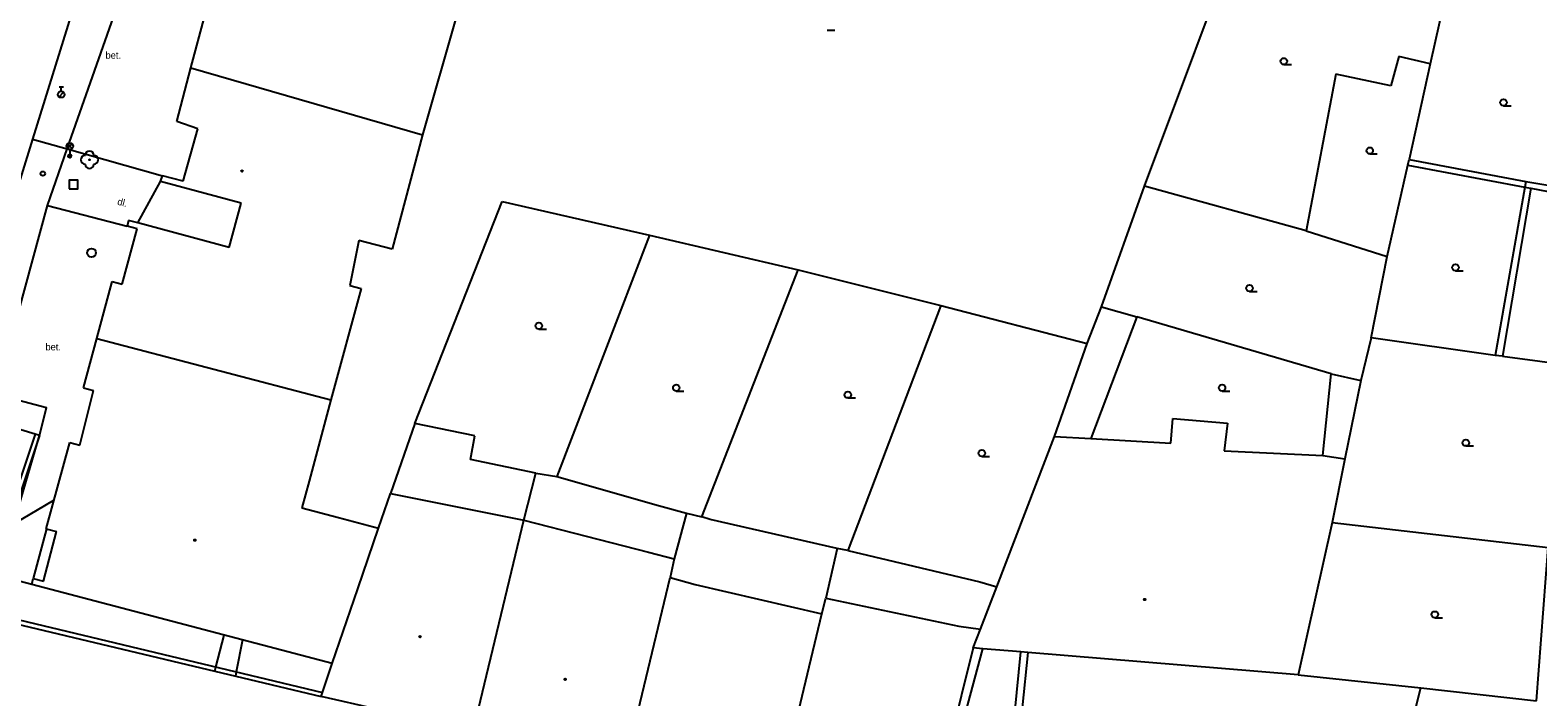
# Model space of a CAD drawing. Extents: x -599770 to -598493, y -1162076 to -1159209.
# Drawn here: x -599476.7 to -599389.9, y -1161736.9 to -1161698.5 of the extents above; entities that cross this region are included whole.
import ezdxf

# ---------------------------------------------------------------- set-up
doc = ezdxf.new("R2010")
doc.units = 0
doc.layers.add('Podklad', color=7, linetype='Continuous')

msp = doc.modelspace()

# ---------------------------------------------------------------- linework, layer by layer
at = {"layer": 'Podklad'}
for p, q in [((-599430.81, -1161698.538), (-599430.372, -1161698.538)), ((-599404.52, -1161700.517), (-599404.082, -1161700.517)), ((-599475.039, -1161702.366), (-599474.774, -1161702.101)), ((-599475.035, -1161701.793), (-599474.785, -1161701.793)), ((-599474.91, -1161702.043), (-599474.91, -1161701.793)), ((-599391.88, -1161702.887), (-599391.442, -1161702.887)), ((-599474.553, -1161705.35), (-599474.288, -1161705.085)), ((-599474.553, -1161705.085), (-599474.288, -1161705.35)), ((-599474.42, -1161705.405), (-599474.42, -1161705.78)), ((-599399.58, -1161705.657), (-599399.142, -1161705.657)), ((-599394.64, -1161712.378), (-599394.203, -1161712.378)), ((-599406.5, -1161713.567), (-599406.062, -1161713.567)), ((-599447.41, -1161715.738), (-599446.972, -1161715.738)), ((-599439.5, -1161719.297), (-599439.062, -1161719.297)), ((-599408.08, -1161719.297), (-599407.642, -1161719.297)), ((-599429.62, -1161719.698), (-599429.183, -1161719.698)), ((-599394.05, -1161722.457), (-599393.613, -1161722.457)), ((-599421.91, -1161723.058), (-599421.472, -1161723.058)), ((-599395.83, -1161732.347), (-599395.392, -1161732.347))]:
    msp.add_line(p, q, dxfattribs=at)
for points in [[(-599475.71, -1161708.62), (-599474.574, -1161705.36), (-599470.317, -1161693.246), (-599469.196, -1161690.055), (-599465.39, -1161677.84)], [(-599472.76, -1161692.57), (-599476.56, -1161704.8)], [(-599412.54, -1161707.52), (-599406.69, -1161691.89)], [(-599394.78, -1161694.54), (-599396.1, -1161700.47)], [(-599467.44, -1161700.7), (-599466.62, -1161697.63)], [(-599452.18, -1161697.79), (-599454.12, -1161704.55)], [(-599397.9, -1161700.05), (-599398.37, -1161701.74)], [(-599396.1, -1161700.47), (-599397.9, -1161700.05)], [(-599396.1, -1161700.47), (-599397.3, -1161705.97)], [(-599468.26, -1161703.79), (-599467.44, -1161700.7)], [(-599467.44, -1161700.7), (-599454.12, -1161704.55)], [(-599401.53, -1161701.06), (-599403.23, -1161710.09)], [(-599398.37, -1161701.74), (-599401.53, -1161701.06)], [(-599467.04, -1161704.22), (-599468.26, -1161703.79)], [(-599476.56, -1161704.8), (-599477.9, -1161709.16), (-599480.87, -1161720.49)], [(-599476.56, -1161704.8), (-599474.574, -1161705.36), (-599469.08, -1161706.91)], [(-599467.89, -1161707.23), (-599467.04, -1161704.22)], [(-599454.12, -1161704.55), (-599455.85, -1161711.14)], [(-599398.57, -1161711.55), (-599397.38, -1161706.31)], [(-599397.38, -1161706.31), (-599397.3, -1161705.97)], [(-599397.38, -1161706.31), (-599390.65, -1161707.57)], [(-599397.3, -1161705.97), (-599390.59, -1161707.25)], [(-599470.5, -1161709.62), (-599469.19, -1161707.24)], [(-599469.19, -1161707.24), (-599469.08, -1161706.91)], [(-599464.56, -1161708.49), (-599469.19, -1161707.24)], [(-599467.89, -1161707.23), (-599469.08, -1161706.91)], [(-599390.59, -1161707.25), (-599390.65, -1161707.57)], [(-599390.59, -1161707.25), (-599388.4, -1161707.6)], [(-599415.03, -1161714.45), (-599412.54, -1161707.52)], [(-599403.23, -1161710.09), (-599412.54, -1161707.52)], [(-599390.65, -1161707.57), (-599392.35, -1161717.25)], [(-599390.3, -1161707.63), (-599391.93, -1161717.29)], [(-599390.65, -1161707.57), (-599390.3, -1161707.63)], [(-599390.3, -1161707.63), (-599386.12, -1161708.43)], [(-599479.09, -1161720.98), (-599478.68, -1161719.49), (-599475.71, -1161708.62)], [(-599475.71, -1161708.62), (-599471.12, -1161709.82)], [(-599465.25, -1161711.04), (-599464.56, -1161708.49)], [(-599454.55, -1161721.16), (-599449.52, -1161708.39)], [(-599449.52, -1161708.39), (-599441.05, -1161710.34)], [(-599471.4, -1161713.15), (-599470.54, -1161709.97)], [(-599471.03, -1161709.48), (-599471.12, -1161709.82)], [(-599470.54, -1161709.97), (-599471.12, -1161709.82)], [(-599465.25, -1161711.04), (-599470.5, -1161709.62), (-599471.03, -1161709.48)], [(-599457.78, -1161710.63), (-599458.29, -1161713.23)], [(-599455.85, -1161711.14), (-599457.78, -1161710.63)], [(-599441.05, -1161710.34), (-599446.37, -1161724.22)], [(-599441.05, -1161710.34), (-599432.49, -1161712.33)], [(-599403.23, -1161710.09), (-599398.57, -1161711.55)], [(-599399.49, -1161716.24), (-599398.57, -1161711.55)], [(-599438.03, -1161726.53), (-599432.49, -1161712.33)], [(-599432.49, -1161712.33), (-599424.27, -1161714.38)], [(-599472.86, -1161716.28), (-599471.98, -1161713)], [(-599471.98, -1161713), (-599471.4, -1161713.15)], [(-599457.64, -1161713.4), (-599459.38, -1161719.8)], [(-599458.29, -1161713.23), (-599457.64, -1161713.4)], [(-599424.27, -1161714.38), (-599429.62, -1161728.47)], [(-599424.27, -1161714.38), (-599415.85, -1161716.56)], [(-599415.85, -1161716.56), (-599415.03, -1161714.45)], [(-599412.98, -1161715.03), (-599415.63, -1161722.03)], [(-599415.03, -1161714.45), (-599412.98, -1161715.03)], [(-599401.79, -1161718.3), (-599412.98, -1161715.03)], [(-599473.63, -1161719.11), (-599472.86, -1161716.28)], [(-599472.86, -1161716.28), (-599459.38, -1161719.8)], [(-599417.73, -1161721.92), (-599415.85, -1161716.56)], [(-599399.49, -1161716.24), (-599400.09, -1161718.7)], [(-599392.35, -1161717.25), (-599399.49, -1161716.24)], [(-599391.93, -1161717.29), (-599392.35, -1161717.25)], [(-599391.93, -1161717.29), (-599385.49, -1161718.16)], [(-599402.28, -1161723), (-599401.79, -1161718.3)], [(-599401.79, -1161718.3), (-599400.09, -1161718.7)], [(-599400.09, -1161718.7), (-599401.01, -1161723.19)], [(-599477.633, -1161726.927), (-599476.17, -1161721.85), (-599475.767, -1161720.261), (-599478.68, -1161719.49)], [(-599473.84, -1161722.41), (-599473.05, -1161719.26)], [(-599473.63, -1161719.11), (-599473.05, -1161719.26)], [(-599459.38, -1161719.8), (-599460.64, -1161724.48)], [(-599476.41, -1161721.77), (-599479.09, -1161720.98)], [(-599454.55, -1161721.16), (-599455.95, -1161725.2)], [(-599451.09, -1161721.88), (-599454.55, -1161721.16)], [(-599411.02, -1161722.3), (-599410.92, -1161720.87)], [(-599410.92, -1161720.87), (-599407.77, -1161721.14)], [(-599407.77, -1161721.14), (-599407.95, -1161722.74)], [(-599476.41, -1161721.77), (-599479.09, -1161729.79)], [(-599476.17, -1161721.85), (-599478.82, -1161729.77), (-599477.34, -1161732.47), (-599459.87, -1161736.65)], [(-599476.17, -1161721.85), (-599476.41, -1161721.77)], [(-599451.35, -1161723.24), (-599451.09, -1161721.88)], [(-599421.04, -1161730.56), (-599417.73, -1161721.92)], [(-599417.73, -1161721.92), (-599415.63, -1161722.03)], [(-599415.63, -1161722.03), (-599411.02, -1161722.3)], [(-599475.77, -1161727.22), (-599474.42, -1161722.26)], [(-599474.42, -1161722.26), (-599473.84, -1161722.41)], [(-599407.95, -1161722.74), (-599402.28, -1161723)], [(-599402.28, -1161723), (-599401.01, -1161723.19)], [(-599447.58, -1161724.02), (-599451.35, -1161723.24)], [(-599401.01, -1161723.19), (-599401.74, -1161726.86)], [(-599460.64, -1161724.48), (-599461.06, -1161726.02)], [(-599448.27, -1161726.72), (-599447.58, -1161724.02)], [(-599447.58, -1161724.02), (-599446.37, -1161724.22)], [(-599446.37, -1161724.22), (-599440.52, -1161725.88)], [(-599476.61, -1161730.42), (-599478.45, -1161729.94), (-599477.63, -1161726.93), (-599475.33, -1161725.57), (-599475.32, -1161725.56)], [(-599456.64, -1161727.18), (-599455.95, -1161725.2)], [(-599455.95, -1161725.2), (-599448.27, -1161726.72)], [(-599461.06, -1161726.02), (-599458.94, -1161726.58)], [(-599440.52, -1161725.88), (-599438.91, -1161726.32)], [(-599438.91, -1161726.32), (-599439.63, -1161728.95)], [(-599438.91, -1161726.32), (-599438.03, -1161726.53)], [(-599475.767, -1161727.221), (-599476.52, -1161730.08)], [(-599475.94, -1161730.23), (-599475.19, -1161727.37)], [(-599475.77, -1161727.22), (-599475.19, -1161727.37)], [(-599458.94, -1161726.58), (-599456.64, -1161727.18)], [(-599457.84, -1161730.67), (-599456.64, -1161727.18)], [(-599451.14, -1161738.62), (-599448.27, -1161726.72)], [(-599448.27, -1161726.72), (-599441.11, -1161728.57)], [(-599437.56, -1161726.69), (-599438.03, -1161726.53)], [(-599430.24, -1161728.35), (-599437.56, -1161726.69)], [(-599401.74, -1161726.86), (-599403.69, -1161735.62)], [(-599401.74, -1161726.86), (-599389.31, -1161728.29)], [(-599441.11, -1161728.57), (-599439.63, -1161728.95)], [(-599439.63, -1161728.95), (-599439.85, -1161730.03)], [(-599430.24, -1161728.35), (-599430.89, -1161731.22)], [(-599429.62, -1161728.47), (-599430.24, -1161728.35)], [(-599429.62, -1161728.47), (-599422.03, -1161730.27)], [(-599389.97, -1161737.13), (-599389.31, -1161728.29)], [(-599476.61, -1161730.42), (-599476.52, -1161730.08)], [(-599459.31, -1161734.98), (-599476.61, -1161730.42)], [(-599476.52, -1161730.08), (-599475.94, -1161730.23)], [(-599459.31, -1161734.98), (-599457.84, -1161730.67)], [(-599442.5, -1161741.05), (-599439.85, -1161730.03)], [(-599439.85, -1161730.03), (-599438.41, -1161730.42)], [(-599438.41, -1161730.42), (-599431.13, -1161732.11)], [(-599422.03, -1161730.27), (-599421.04, -1161730.56)], [(-599421.98, -1161733), (-599421.04, -1161730.56)], [(-599431.13, -1161732.11), (-599430.89, -1161731.22)], [(-599430.89, -1161731.22), (-599423.24, -1161732.82)], [(-599433.7, -1161742.87), (-599431.13, -1161732.11)], [(-599477.51, -1161732.69), (-599459.95, -1161736.88)], [(-599466.074, -1161735.419), (-599466.012, -1161735.18), (-599465.529, -1161733.341)], [(-599423.24, -1161732.82), (-599421.98, -1161733)], [(-599422.4, -1161734.08), (-599421.98, -1161733)], [(-599464.483, -1161733.617), (-599464.839, -1161735.461), (-599464.886, -1161735.702)], [(-599422.4, -1161734.08), (-599425.13, -1161745.05)], [(-599424.54, -1161744.83), (-599423.25, -1161739.32), (-599421.85, -1161734.12)], [(-599421.85, -1161734.12), (-599422.4, -1161734.08)], [(-599419.66, -1161734.3), (-599421.85, -1161734.12)], [(-599420.25, -1161740.15), (-599419.66, -1161734.3)], [(-599419.26, -1161734.34), (-599419.66, -1161734.3)], [(-599459.87, -1161736.65), (-599459.31, -1161734.98)], [(-599419.26, -1161734.34), (-599419.58, -1161737.52)], [(-599403.69, -1161735.62), (-599419.26, -1161734.34)], [(-599403.69, -1161735.62), (-599396.63, -1161736.37)], [(-599459.95, -1161736.88), (-599459.87, -1161736.65)], [(-599456.75, -1161737.6), (-599459.95, -1161736.88)], [(-599397.48, -1161739.72), (-599396.63, -1161736.37)], [(-599396.63, -1161736.37), (-599389.97, -1161737.13)]]:
    msp.add_lwpolyline(points, dxfattribs=at)
msp.add_lwpolyline([(-599474.46, -1161707.66), (-599473.96, -1161707.66), (-599473.96, -1161707.16), (-599474.46, -1161707.16)], close=True, dxfattribs=at)
for centre, radius in [((-599404.52, -1161700.33), 0.188), ((-599474.91, -1161702.23), 0.188), ((-599391.88, -1161702.7), 0.188), ((-599474.42, -1161705.218), 0.188), ((-599474.42, -1161705.78), 0.1), ((-599399.58, -1161705.47), 0.188), ((-599474.42, -1161705.78), 0.0723), ((-599474.42, -1161705.78), 0.0438), ((-599473.28, -1161705.99), 0.025), ((-599475.97, -1161706.79), 0.125), ((-599464.5, -1161706.64), 0.045), ((-599464.5, -1161706.64), 0.0199), ((-599473.16, -1161711.34), 0.25), ((-599394.64, -1161712.19), 0.188), ((-599406.5, -1161713.38), 0.188), ((-599447.41, -1161715.55), 0.188), ((-599439.5, -1161719.11), 0.188), ((-599429.62, -1161719.51), 0.188), ((-599408.08, -1161719.11), 0.188), ((-599394.05, -1161722.27), 0.188), ((-599421.91, -1161722.87), 0.188), ((-599467.22, -1161727.88), 0.045), ((-599467.22, -1161727.88), 0.0199), ((-599412.53, -1161731.29), 0.045), ((-599412.53, -1161731.29), 0.0199), ((-599395.83, -1161732.16), 0.188), ((-599454.25, -1161733.43), 0.045), ((-599454.25, -1161733.43), 0.0199), ((-599445.9, -1161735.89), 0.045), ((-599445.9, -1161735.89), 0.0199)]:
    msp.add_circle(centre, radius, dxfattribs=at)
for centre, start, end in [((-599473.28, -1161705.74), 0, 180), ((-599473.53, -1161705.99), 90, 270), ((-599473.28, -1161706.24), 180, 0), ((-599473.03, -1161705.99), 270, 90)]:
    msp.add_arc(centre, 0.25, start, end, dxfattribs=at)

# ---------------------------------------------------------------- texts
for p in [(-599472.36, -1161700.18), (-599475.82, -1161716.96)]:
    msp.add_text('bet.', height=0.4, dxfattribs=at).set_placement(p)
msp.add_text('dl.', height=0.4, rotation=345.56, dxfattribs=at).set_placement((-599471.71, -1161708.57))

doc.saveas('drawing.dxf')
